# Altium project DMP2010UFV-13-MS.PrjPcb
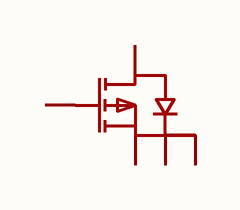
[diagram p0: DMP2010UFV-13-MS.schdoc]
1 sheet, 1 parts. Net scope: global (net labels, ports and power ports of the same name join across sheets).

## Sheet DMP2010UFV-13-MS.schdoc
size 127 x 101 mm

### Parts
Q?  dmp2010ufv-13-ms  [PDFN3333-8_L3.1-W3.2-P0.65-LS3.4-BL_1]  (value not drawn)

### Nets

Not connected (* = marked no-connect by the designer): Q? 1(S) 2(S) 3(S) 4(G) 5(D)

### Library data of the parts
Q? = dmp2010ufv-13-ms: 数量:1个P沟道;漏源电压(Vdss):20V;连续漏极电流(Id):60A;导通电阻(RDS(on)):7mΩ@4.5V;耗散功率(Pd):22W;阈值电压(Vgs(th)):700mV;; Manufacturer: MSKSEMI(美森科); AddInBom: yes; ModelId: c288237aeb774e1d92142cc9eea176d4; ModelTransform: 118.8974,118.8974,0,90,0,0,0,19.486,0; Number: 1个P沟道; Drain to Source Voltage: 20V; Current - Continuous Drain(Id): 60A; Pd - Power Dissipation: 22W; Gate Threshold Voltage (Vgs(th)): 700mV; Gate Charge(Qg): 35nC; Input Capacitance(Ciss): 2.8nF; Reverse Transfer Capacitance (Crss@Vds): 590pF; Type: P沟道; Output Capacitance(Coss): 690pF; Vgs: ±12V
